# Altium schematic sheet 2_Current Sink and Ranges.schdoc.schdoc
size 431 x 309 mm; Symbol: Sheet-Symbol-Custom; Device: Sheet-Symbol-Custom; @Page Count: 4; @Create Date: 2024-03-28; Drawn: Thomas Crisafulli; @Page No: 3; @Page Name: Current Sink and Ranges.Schematic 1; @Project Name: OhmmeterV3.0_Release; @Schematic Name: Schematic 1; Page Size: A3; @Update Date: 2024-03-27
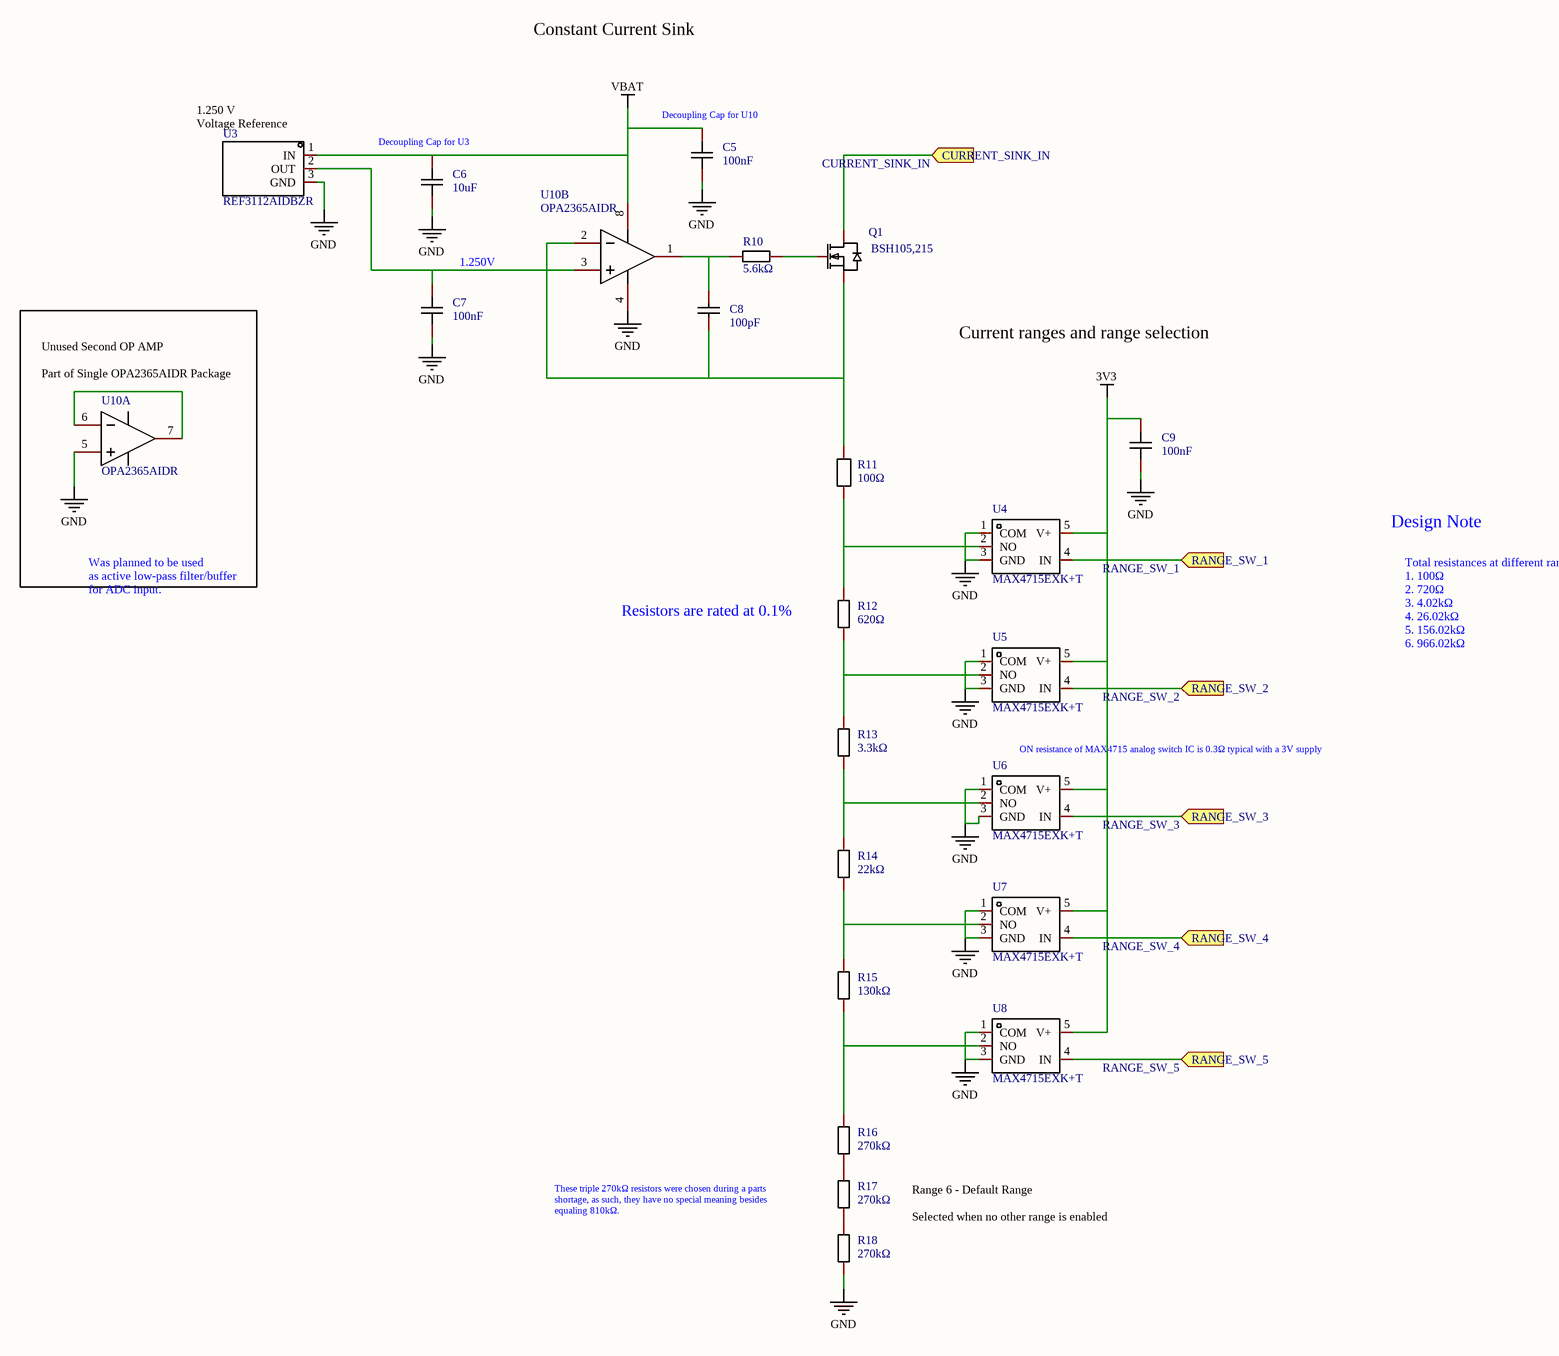
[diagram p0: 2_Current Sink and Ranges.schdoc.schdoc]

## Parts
C5  100nF  [C0603]
C6  10uF  [C0603]
C7  100nF  [C0603]
C8  100pF  [C0603]
C9  100nF  [C0603]
Q1  BSH105,215  [TO-236AB_L2.9-W1.3-P0.95-LS2.3-BR]
R10  5.6kΩ  [R0603]
R11  100Ω  [R0805]
R12  620Ω  [R0805]
R13  3.3kΩ  [R0805]
R14  22kΩ  [R0805]
R15  130kΩ  [R0805]
R16  270kΩ  [R0805]
R17  270kΩ  [R0805]
R18  270kΩ  [R0805]
U3  REF3112AIDBZR  [SOT-23-3_L2.9-W1.6-P1.90-LS2.8-BR]
U4  MAX4715EXK+T  [SC-70-5_L2.0-W1.3-P0.65-LS2.1-BR]
U5  MAX4715EXK+T  [SC-70-5_L2.0-W1.3-P0.65-LS2.1-BR]
U6  MAX4715EXK+T  [SC-70-5_L2.0-W1.3-P0.65-LS2.1-BR]
U7  MAX4715EXK+T  [SC-70-5_L2.0-W1.3-P0.65-LS2.1-BR]
U8  MAX4715EXK+T  [SC-70-5_L2.0-W1.3-P0.65-LS2.1-BR]
U10  OPA2365AIDR  [SOIC-8_L4.9-W3.9-P1.27-LS6.0-BL]  (parts A,B of 2)

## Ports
CURRENT_SINK_IN (in), RANGE_SW_1 (in), RANGE_SW_2 (in), RANGE_SW_3 (in), RANGE_SW_4 (in), RANGE_SW_5 (in)

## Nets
3V3: C9.2 U4.5(V+) U5.5(V+) U6.5(V+) U7.5(V+) U8.5(V+)
GND: C5.1 C6.1 C7.2 C9.1 R18.1 U3.3(GND) U4.1(COM) U4.3(GND) U5.1(COM) U5.3(GND) U6.1(COM) U6.3(GND) U7.1(COM) U7.3(GND) U8.1(COM) U8.3(GND) U10.4(V-) U10.5(IN_B+)
VBAT: C5.2 C6.2 U3.1(IN) U10.8(V+)
1.250V: C7.1 U3.2(OUT) U10.3(IN_A+)
CURRENT_SINK_IN: Q1.3(D) ; port CURRENT_SINK_IN
RANGE_SW_1: U4.4(IN) ; port RANGE_SW_1
RANGE_SW_2: U5.4(IN) ; port RANGE_SW_2
RANGE_SW_3: U6.4(IN) ; port RANGE_SW_3
RANGE_SW_4: U7.4(IN) ; port RANGE_SW_4
RANGE_SW_5: U8.4(IN) ; port RANGE_SW_5
NetC8_1: C8.1 R10.2 U10.1(VOUT_A)
NetC8_2: C8.2 Q1.2(S) R11.2 U10.2(IN_A-)
NetQ1_1: Q1.1(G) R10.1
NetR11_1: R11.1 R12.2 U4.2(NO)
NetR12_1: R12.1 R13.2 U5.2(NO)
NetR13_1: R13.1 R14.2 U6.2(NO)
NetR14_1: R14.1 R15.2 U7.2(NO)
NetR15_1: R15.1 R16.2 U8.2(NO)
NetR16_1: R16.1 R17.2
NetR17_1: R17.1 R18.2
NetU10_6: U10.6(IN_B-) U10.7(VOUT_B)

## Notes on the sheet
- Constant Current Sink
- (near U3) 1.250 V
  Voltage Reference
- (near C6) Decoupling Cap for U3
- (near C5) Decoupling Cap for U10
- (near U10) Unused Second OP AMP
  Part of Single OPA2365AIDR Package
- Current ranges and range selection
- Was planned to be used
  as active low-pass filter/buffer
  for ADC input.
- Design Note
- Total resistances at different ranges:
  1. 100Ω
  2. 720Ω
  3. 4.02kΩ
  4. 26.02kΩ
  5. 156.02kΩ
  6. 966.02kΩ
- (near R12) Resistors are rated at 0.1%
- (near U6) ON resistance of MAX4715 analog switch IC is 0.3Ω typical with a 3V supply
- These triple 270kΩ resistors were chosen during a parts
  shortage, as such, they have no special meaning besides
  equaling 810kΩ.
- Range 6 - Default Range
  Selected when no other range is enabled

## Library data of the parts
C5 C7 C9 = CC0603KRX7R9BB104: Manufacturer: YAGEO(国巨); Add into BOM: yes; Tolerance: ±10%; Description: Capacitance: Tolerance:±10% Tolerance:±10% Voltage Rated: Temperature Coefficient:
C6 = CL10A106KP8NNNC: Manufacturer: SAMSUNG(三星); Add into BOM: yes; Tolerance: ±10%; Description: Capacitance: Tolerance:±10% Tolerance:±10% Voltage Rated: Temperature Coefficient:
C8 = 0603CG101F500NT: Manufacturer: FH(风华); Add into BOM: yes; Tolerance: ±1%; Description: Capacitance: Tolerance:±1% Tolerance:±1% Voltage Rated: Temperature Coefficient:
Q1 = BSH105,215: Manufacturer: Nexperia(安世); Add into BOM: yes; Drain Source On Resistance (RDS(on)@Vgs,Id): 200mΩ@4.5V,600mA; Gate Threshold Voltage (Vgs(th)@Id): 570mV@1mA; Description: Type: Drain Source Voltage (Vdss): Continuous Drain Current (Id): Power Dissipation (Pd): Drain Source On Resistance (RDS(on)@Vgs,Id):200mΩ@4.5V,600mA Gate Threshold Voltage (Vgs(th)@Id):570mV@1mA
R10 = RMC06035.6K1%N: Manufacturer: Tyohm(幸亚电阻); Add into BOM: yes; Tolerance: ±1%; Power(Watts): 0.1W; Description: Resistance:5.6kΩ Tolerance:±1% Power(Watts):0.1W
R11 = RT0805BRB07100RL: Type:Thin Film Resistor Resistance: Tolerance:±0.1% Tolerance:±0.1% Power(Watts): Temperature Coefficient:±10ppm/ Temperature Coefficient:±10ppm/ Overload Voltage (Max): Operating Temperature Range:-55~+155 Operating Temperature Range:-55~+155; Manufacturer: YAGEO(国巨); Add into BOM: yes; Tolerance: ±0.1%; Temperature Coefficient: ±10ppm/
R12 = PTFR0805B620RN9: Type:Thin Film Resistor Resistance: Tolerance:±0.1% Tolerance:±0.1% Power(Watts): Temperature Coefficient:±10ppm/ Temperature Coefficient:±10ppm/ Overload Voltage (Max): Operating Temperature Range:-55~+125 Operating Temperature Range:-55~+125; Manufacturer: RESI(开步睿思）; Add into BOM: yes; Tolerance: ±0.1%; Temperature Coefficient: ±10ppm/
R13 = PTFR0805B3K30N9: Type:Thin Film Resistor Resistance: Tolerance:±0.1% Tolerance:±0.1% Power(Watts): Temperature Coefficient:±10ppm/ Temperature Coefficient:±10ppm/ Overload Voltage (Max): Operating Temperature Range:-55~+125 Operating Temperature Range:-55~+125; Manufacturer: RESI(开步睿思）; Add into BOM: yes; Tolerance: ±0.1%; Temperature Coefficient: ±10ppm/
R14 = PTFR0805B22K0N9: Type:Thin Film Resistor Resistance: Tolerance:±0.1% Tolerance:±0.1% Power(Watts): Temperature Coefficient:±10ppm/ Temperature Coefficient:±10ppm/ Overload Voltage (Max): Operating Temperature Range:-55~+125 Operating Temperature Range:-55~+125; Manufacturer: RESI(开步睿思）; Add into BOM: yes; Tolerance: ±0.1%; Temperature Coefficient: ±10ppm/
R15 = PTFR0805B130KN9: Type:Thin Film Resistor Resistance: Tolerance:±0.1% Tolerance:±0.1% Power(Watts): Temperature Coefficient:±10ppm/ Temperature Coefficient:±10ppm/ Overload Voltage (Max): Operating Temperature Range:-55~+125 Operating Temperature Range:-55~+125; Manufacturer: RESI(开步睿思）; Add into BOM: yes; Tolerance: ±0.1%; Temperature Coefficient: ±10ppm/
R16-R18 = PTFR0805B270KN9: Type:Thin Film Resistor Resistance: Tolerance:±0.1% Tolerance:±0.1% Power(Watts): Temperature Coefficient:±10ppm/ Temperature Coefficient:±10ppm/ Overload Voltage (Max): Operating Temperature Range:-55~+125 Operating Temperature Range:-55~+125; Manufacturer: RESI(开步睿思）; Add into BOM: yes; Tolerance: ±0.1%; Temperature Coefficient: ±10ppm/
U3 = REF3112AIDBZR: Reference Type:series connection Output Type:Fixed Input Voltage:1.8V~5.5V Input Voltage:1.8V~5.5V Output Current:10mA Tolerance:±0.2% Tolerance:±0.2% Temperature Coefficient:20ppm/ Supply Current:135uA Noise - 1/10Hz to 10Hz:17uVp-p Noise - 10Hz to 10kH; Manufacturer: TI(德州仪器); Add into BOM: yes; Output Type: Fixed; Output Current: 10mA; Tolerance: ±0.2%; Temperature Coefficient: 20ppm/; Supply Current: 135uA; Noise - 10Hz to 10kHz: 24uVrms
U4-U8 = MAX4715EXK+T: Manufacturer: MAXIM(美信); Add into BOM: yes; Description: Switch Circuit:- Multiplexer/Demultiplexer Circuit:- Number of Circuits:- On Resistance (Max):- Switch Voltage (Max):- On Time (Max):- Off Time (Max):- Supply Voltage:- Operating Temperature:-
U10 = OPA2365AIDR: Manufacturer: TI(德州仪器); Add into BOM: yes; Amplifier Type: High-speedbroadbandamplifier; Current - Input Bias（Ib）: 0.2pA; Voltage - Input Offset（Vos）: 100uV; Output Type: Rail-to-Rail; Description: Amplifier Type:High-speedbroadbandamplifier Number of Circuits: -3db Bandwidth（G=1）:- Current - Input Bias（Ib）:0.2pA Voltage - Input Offset（Vos）:100uV Gain Bandwidth Product（GBP）: Slew Rate（SR）: Output Type:Rail-to-Rail Supply Voltage（Single）: Iq per chan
